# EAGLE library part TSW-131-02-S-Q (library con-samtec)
THROUGH-HOLE .025" SQ POST HEADER Source: Samtec TSW.pdf
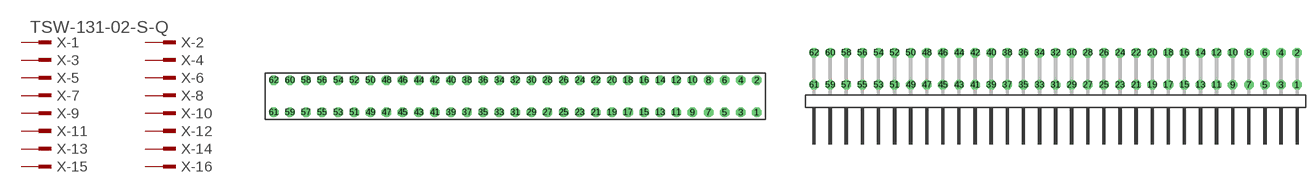
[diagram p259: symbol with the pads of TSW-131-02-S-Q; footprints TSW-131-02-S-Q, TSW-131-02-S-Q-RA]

Designator prefix X; gates -1=MPINV -2=MPIN -3=MPIN -4=MPIN -5=MPIN -6=MPIN -7=MPIN -8=MPIN -9=MPIN -10=MPIN -11=MPIN -12=MPIN -13=MPIN -14=MPIN -15=MPIN -16=MPIN -17=MPIN -18=MPIN -19=MPIN -20=MPIN -21=MPIN -22=MPIN -23=MPIN -24=MPIN -25=MPIN -26=MPIN -27=MPIN -28=MPIN -29=MPIN -30=MPIN -31=MPIN -32=MPIN -33=MPIN -34=MPIN -35=MPIN -36=MPIN -37=MPIN -38=MPIN -39=MPIN -40=MPIN -41=MPIN -42=MPIN -43=MPIN -44=MPIN -45=MPIN -46=MPIN -47=MPIN -48=MPIN -49=MPIN -50=MPIN -51=MPIN -52=MPIN -53=MPIN -54=MPIN -55=MPIN -56=MPIN -57=MPIN -58=MPIN -59=MPIN -60=MPIN -61=MPIN -62=MPIN

## TSW-131-02-S-Q (OC_FARNELL: unknown; OC_NEWARK: unknown)  [TSW-131-02-S-Q]
1  -1:1  pas
2  -2:1  pas
3  -3:1  pas
4  -4:1  pas
5  -5:1  pas
6  -6:1  pas
7  -7:1  pas
8  -8:1  pas
9  -9:1  pas
10  -10:1  pas
11  -11:1  pas
12  -12:1  pas
13  -13:1  pas
14  -14:1  pas
15  -15:1  pas
16  -16:1  pas
17  -17:1  pas
18  -18:1  pas
19  -19:1  pas
20  -20:1  pas
21  -21:1  pas
22  -22:1  pas
23  -23:1  pas
24  -24:1  pas
25  -25:1  pas
26  -26:1  pas
27  -27:1  pas
28  -28:1  pas
29  -29:1  pas
30  -30:1  pas
31  -31:1  pas
32  -32:1  pas
33  -33:1  pas
34  -34:1  pas
35  -35:1  pas
36  -36:1  pas
37  -37:1  pas
38  -38:1  pas
39  -39:1  pas
40  -40:1  pas
41  -41:1  pas
42  -42:1  pas
43  -43:1  pas
44  -44:1  pas
45  -45:1  pas
46  -46:1  pas
47  -47:1  pas
48  -48:1  pas
49  -49:1  pas
50  -50:1  pas
51  -51:1  pas
52  -52:1  pas
53  -53:1  pas
54  -54:1  pas
55  -55:1  pas
56  -56:1  pas
57  -57:1  pas
58  -58:1  pas
59  -59:1  pas
60  -60:1  pas
61  -61:1  pas
62  -62:1  pas

## TSW-131-02-S-Q-RA (OC_FARNELL: unknown; OC_NEWARK: unknown)  [TSW-131-02-S-Q-RA]
Pads as for TSW-131-02-S-Q

## Footprint TSW-131-02-S-Q (pad centres in mm)
THROUGH-HOLE .025" SQ POST HEADER Source: Samtec TSW.pdf
drill 1 pad 1.5 octagon: 1 38.1,-2.54; 2 38.1,2.54; 3 35.56,-2.54; 4 35.56,2.54; 5 33.02,-2.54; 6 33.02,2.54; 7 30.48,-2.54; 8 30.48,2.54; 9 27.94,-2.54; 10 27.94,2.54; 11 25.4,-2.54; 12 25.4,2.54; 13 22.86,-2.54; 14 22.86,2.54; 15 20.32,-2.54; 16 20.32,2.54; 17 17.78,-2.54; 18 17.78,2.54; 19 15.24,-2.54; 20 15.24,2.54; 21 12.7,-2.54; 22 12.7,2.54; 23 10.16,-2.54; 24 10.16,2.54; 25 7.62,-2.54; 26 7.62,2.54; 27 5.08,-2.54; 28 5.08,2.54; 29 2.54,-2.54; 30 2.54,2.54; 31 0,-2.54; 32 0,2.54; 33 -2.54,-2.54; 34 -2.54,2.54; 35 -5.08,-2.54; 36 -5.08,2.54; 37 -7.62,-2.54; 38 -7.62,2.54; 39 -10.16,-2.54; 40 -10.16,2.54; 41 -12.7,-2.54; 42 -12.7,2.54; 43 -15.24,-2.54; 44 -15.24,2.54; 45 -17.78,-2.54; 46 -17.78,2.54; 47 -20.32,-2.54; 48 -20.32,2.54; 49 -22.86,-2.54; 50 -22.86,2.54; 51 -25.4,-2.54; 52 -25.4,2.54; 53 -27.94,-2.54; 54 -27.94,2.54; 55 -30.48,-2.54; 56 -30.48,2.54; 57 -33.02,-2.54; 58 -33.02,2.54; 59 -35.56,-2.54; 60 -35.56,2.54; 61 -38.1,-2.54; 62 -38.1,2.54

## Footprint TSW-131-02-S-Q-RA (pad centres in mm)
THROUGH-HOLE .025" SQ POST HEADER Source: Samtec TSW.pdf
drill 1 pad 1.5 octagon: 1 38.1,1.524; 2 38.1,6.604; 3 35.56,1.524; 4 35.56,6.604; 5 33.02,1.524; 6 33.02,6.604; 7 30.48,1.524; 8 30.48,6.604; 9 27.94,1.524; 10 27.94,6.604; 11 25.4,1.524; 12 25.4,6.604; 13 22.86,1.524; 14 22.86,6.604; 15 20.32,1.524; 16 20.32,6.604; 17 17.78,1.524; 18 17.78,6.604; 19 15.24,1.524; 20 15.24,6.604; 21 12.7,1.524; 22 12.7,6.604; 23 10.16,1.524; 24 10.16,6.604; 25 7.62,1.524; 26 7.62,6.604; 27 5.08,1.524; 28 5.08,6.604; 29 2.54,1.524; 30 2.54,6.604; 31 0,1.524; 32 0,6.604; 33 -2.54,1.524; 34 -2.54,6.604; 35 -5.08,1.524; 36 -5.08,6.604; 37 -7.62,1.524; 38 -7.62,6.604; 39 -10.16,1.524; 40 -10.16,6.604; 41 -12.7,1.524; 42 -12.7,6.604; 43 -15.24,1.524; 44 -15.24,6.604; 45 -17.78,1.524; 46 -17.78,6.604; 47 -20.32,1.524; 48 -20.32,6.604; 49 -22.86,1.524; 50 -22.86,6.604; 51 -25.4,1.524; 52 -25.4,6.604; 53 -27.94,1.524; 54 -27.94,6.604; 55 -30.48,1.524; 56 -30.48,6.604; 57 -33.02,1.524; 58 -33.02,6.604; 59 -35.56,1.524; 60 -35.56,6.604; 61 -38.1,1.524; 62 -38.1,6.604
